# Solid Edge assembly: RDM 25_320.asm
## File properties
Title: Zylinder
Author: ahadarics
Template: iso metric assembly.asm
Last saved by: ahadarics
Revision: 28
Application: Solid Edge
Username: ahadarics
Dokumentum tartalom típus: 1
Document Number: RDM 25/320
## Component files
Profilrohr.par
Kolbenstange.par
Kit_1.par
Kit_2.par
Mutter_1.par
Mutter_2.par
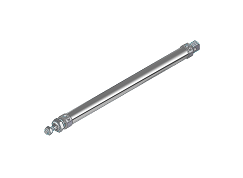
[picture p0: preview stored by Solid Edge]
